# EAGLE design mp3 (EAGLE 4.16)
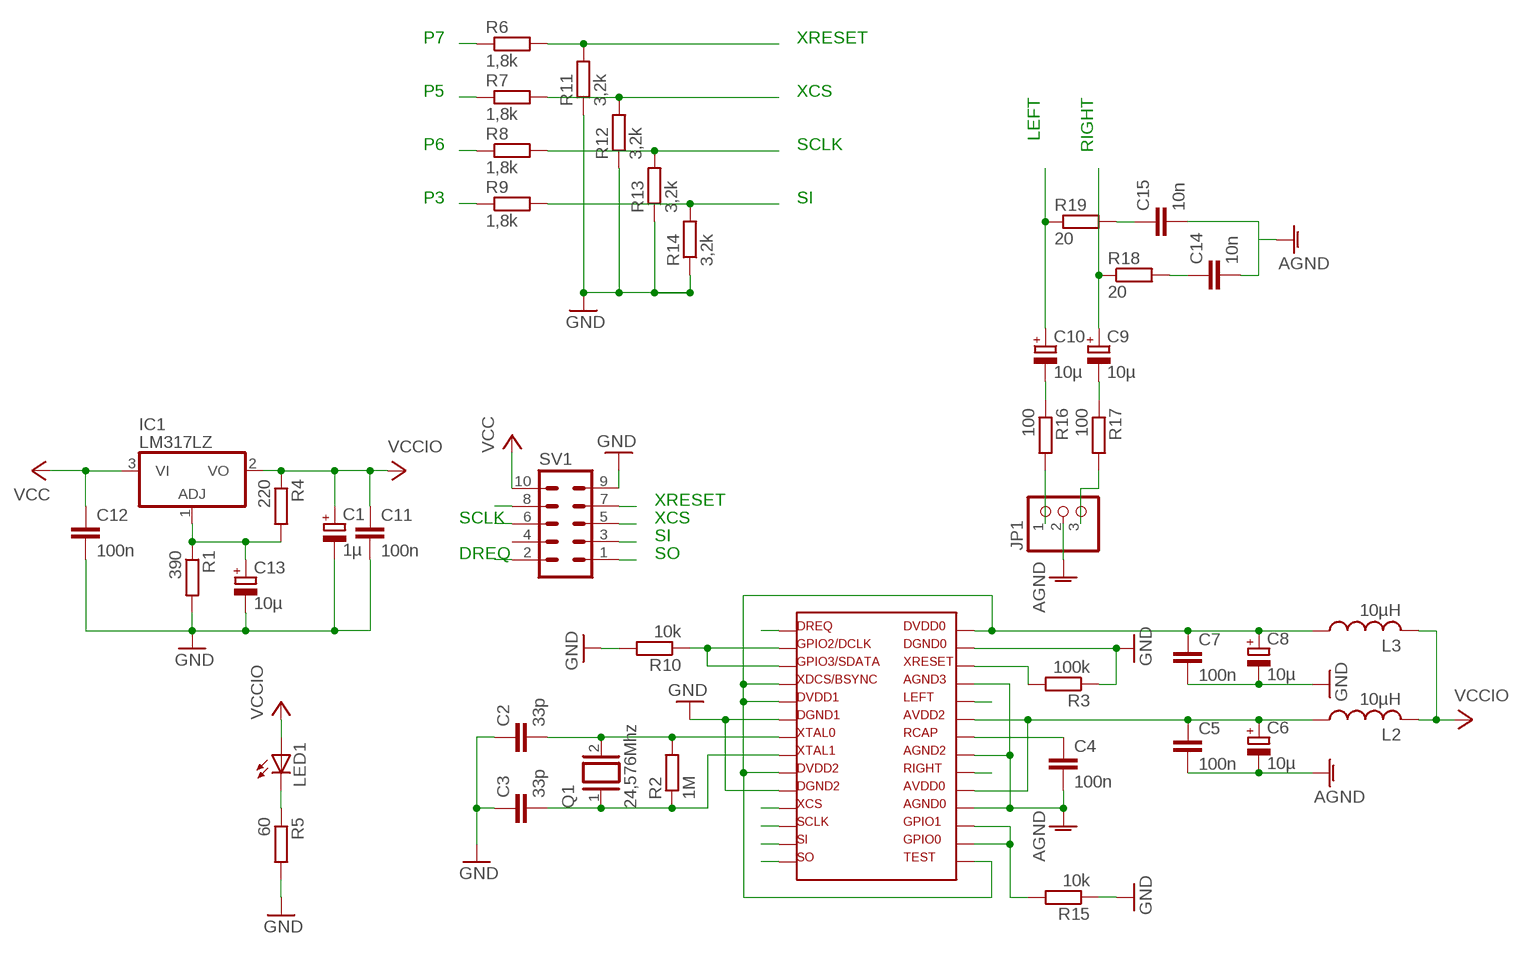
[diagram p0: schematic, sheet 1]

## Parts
C1  1µ  CPOL-EUE1.8-4  [E1,8-4]
C2  33p  C-EUC1206  [C1206]
C3  33p  C-EUC1206  [C1206]
C4  100n  C-EUC1206  [C1206]
C5  100n  C-EUC1206  [C1206]
C6  10µ  CPOL-EUE1.8-4  [E1,8-4]
C7  100n  C-EUC1206  [C1206]
C8  10µ  CPOL-EUE1.8-4  [E1,8-4]
C9  10µ  CPOL-EUE2.5-6  [E2,5-6]
C10  10µ  CPOL-EUE2.5-6  [E2,5-6]
C11  100n  C-EUC1206  [C1206]
C12  100n  C-EUC1206  [C1206]
C13  10µ  CPOL-EUE1.8-4  [E1,8-4]
C14  10n  C-EUC1206  [C1206]
C15  10n  C-EUC1206  [C1206]
IC1  LM317LZ  [TO92]
JP1  PINHD-1X3  [1X03]
L2  10µH  L-US0207/12  [0207/12]
L3  10µH  L-US0207/12  [0207/12]
LED1  LED3MM  [LED3MM]
Q1  24,576Mhz  XTAL/S  [QS]
R1  390  R-EU_M1206  [M1206]
R2  1M  R-EU_M1206  [M1206]
R3  100k  R-EU_M1206  [M1206]
R4  220  R-EU_M1206  [M1206]
R5  60  R-EU_M1206  [M1206]
R6  1,8k  R-EU_M1206  [M1206]
R7  1,8k  R-EU_M1206  [M1206]
R8  1,8k  R-EU_M1206  [M1206]
R9  1,8k  R-EU_M1206  [M1206]
R10  10k  R-EU_M1206  [M1206]
R11  3,2k  R-EU_M1206  [M1206]
R12  3,2k  R-EU_M1206  [M1206]
R13  3,2k  R-EU_M1206  [M1206]
R14  3,2k  R-EU_M1206  [M1206]
R15  10k  R-EU_M1206  [M1206]
R16  100  R-EU_M1206  [M1206]
R17  100  R-EU_M1206  [M1206]
R18  20  R-EU_M1206  [M1206]
R19  20  R-EU_M1206  [M1206]
SV1  ML10  [ML10]
U$1  VS1011  [SOIC-28]

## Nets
AGND: C4.2 C5.2 C6.- C14.2 C15.2 JP1.2 U$1.18 U$1.21 U$1.25
AVDD: C5.1 C6.+ L2.1 U$1.19 U$1.23
DREQ: SV1.2 U$1.1
DVDD: C7.1 C8.+ L3.1 U$1.4 U$1.5 U$1.9 U$1.15 U$1.28
GND: C1.- C2.1 C3.1 C7.2 C8.- C11.2 C12.2 C13.- R1.2 R3.1 R5.2 R10.2 R11.1 R12.1 R13.1 R14.1 R15.1 SV1.9 U$1.6 U$1.10 U$1.27
LEFT: C10.+ R19.1 U$1.24
N$1: C2.2 Q1.2 R2.2 U$1.7
N$2: C3.2 Q1.1 R2.1 U$1.8
N$3: C10.- R16.1
N$4: C4.1 U$1.22
N$5: JP1.3 R17.2
N$6: C13.+ IC1.1(ADJ) R1.1 R4.2
N$10: C9.- R17.1
N$11: LED1.K(C) R5.1
N$12: R10.1 U$1.2 U$1.3
N$13: R15.2 U$1.16 U$1.17
N$14: C15.1 R19.2
N$15: C14.1 R18.2
N$16: JP1.1 R16.2
P3: R9.1 SV1.3
P5: R7.1 SV1.5
P6: R8.1 SV1.6
P7: R6.1 SV1.7
P8: SV1.8
RIGHT: C9.+ R18.1 U$1.20
SCLK: R8.2 R13.2 U$1.12
SI: R9.2 R14.2 U$1.13
SO: SV1.1 U$1.14
VCC: C12.1 IC1.3(VI) SV1.10
VCCIO: C1.+ C11.1 IC1.2(VO) L2.2 L3.2 LED1.A R4.1
XCS: R7.2 R12.2 U$1.11
XRESET: R3.2 R6.2 R11.2 U$1.26
Unconnected: SV1.4

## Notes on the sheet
- P7 | XRESET
- P5 | XCS | LEFT | RIGHT
- P6 | SCLK
- P3 | SI
- XRESET
- SCLK | XCS
- SI
- DREQ | SO

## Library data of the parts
C1 C6 C8-C10 C13 = rcl:CPOL-EU: POLARIZED CAPACITOR, European symbol
C2-C5 C7 C11 C12 C14 C15 = rcl:C-EU: CAPACITOR, European symbol
IC1 = linear:*317: Positive VOLTAGE REGULATOR
JP1 = pinhead:PINHD-1X3: PIN HEADER
L2 L3 = rcl:L-US: INDUCTOR, American symbol
LED1 = led:LED: LED
Q1 = special:XTAL/S: CRYSTAL
R1-R19 = rcl:R-EU_: RESISTOR, European symbol
SV1 = con-ml:ML10: HARTING
U$1 = vs10xx:VS1011

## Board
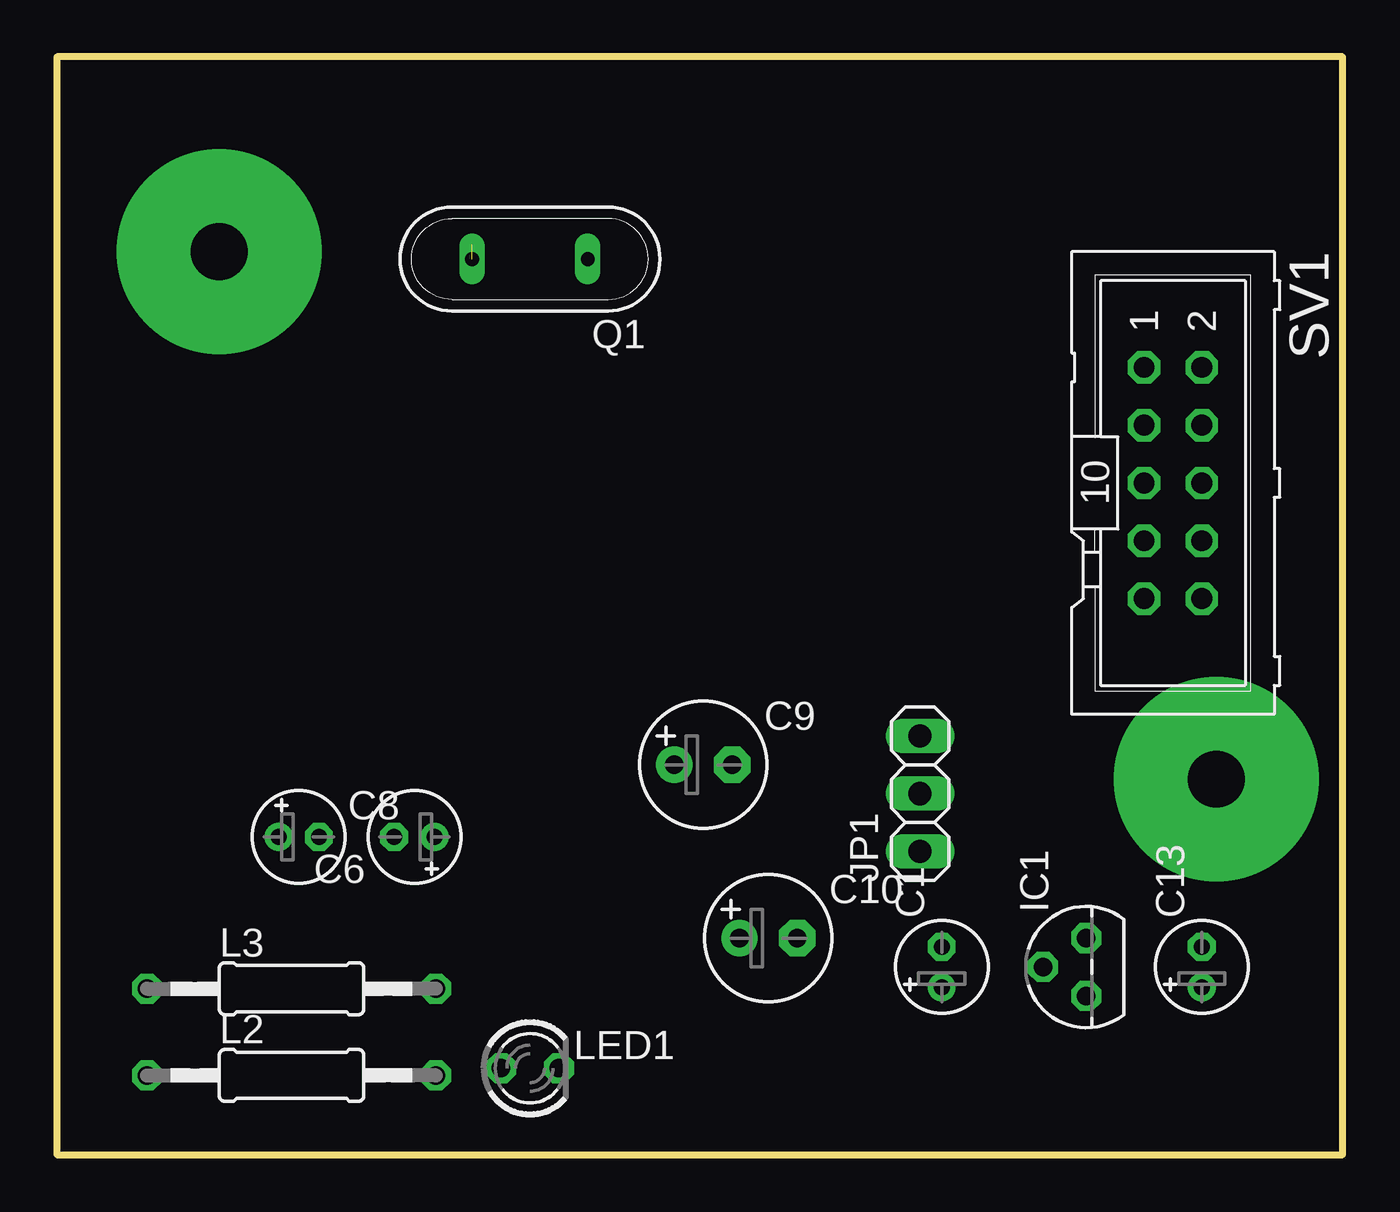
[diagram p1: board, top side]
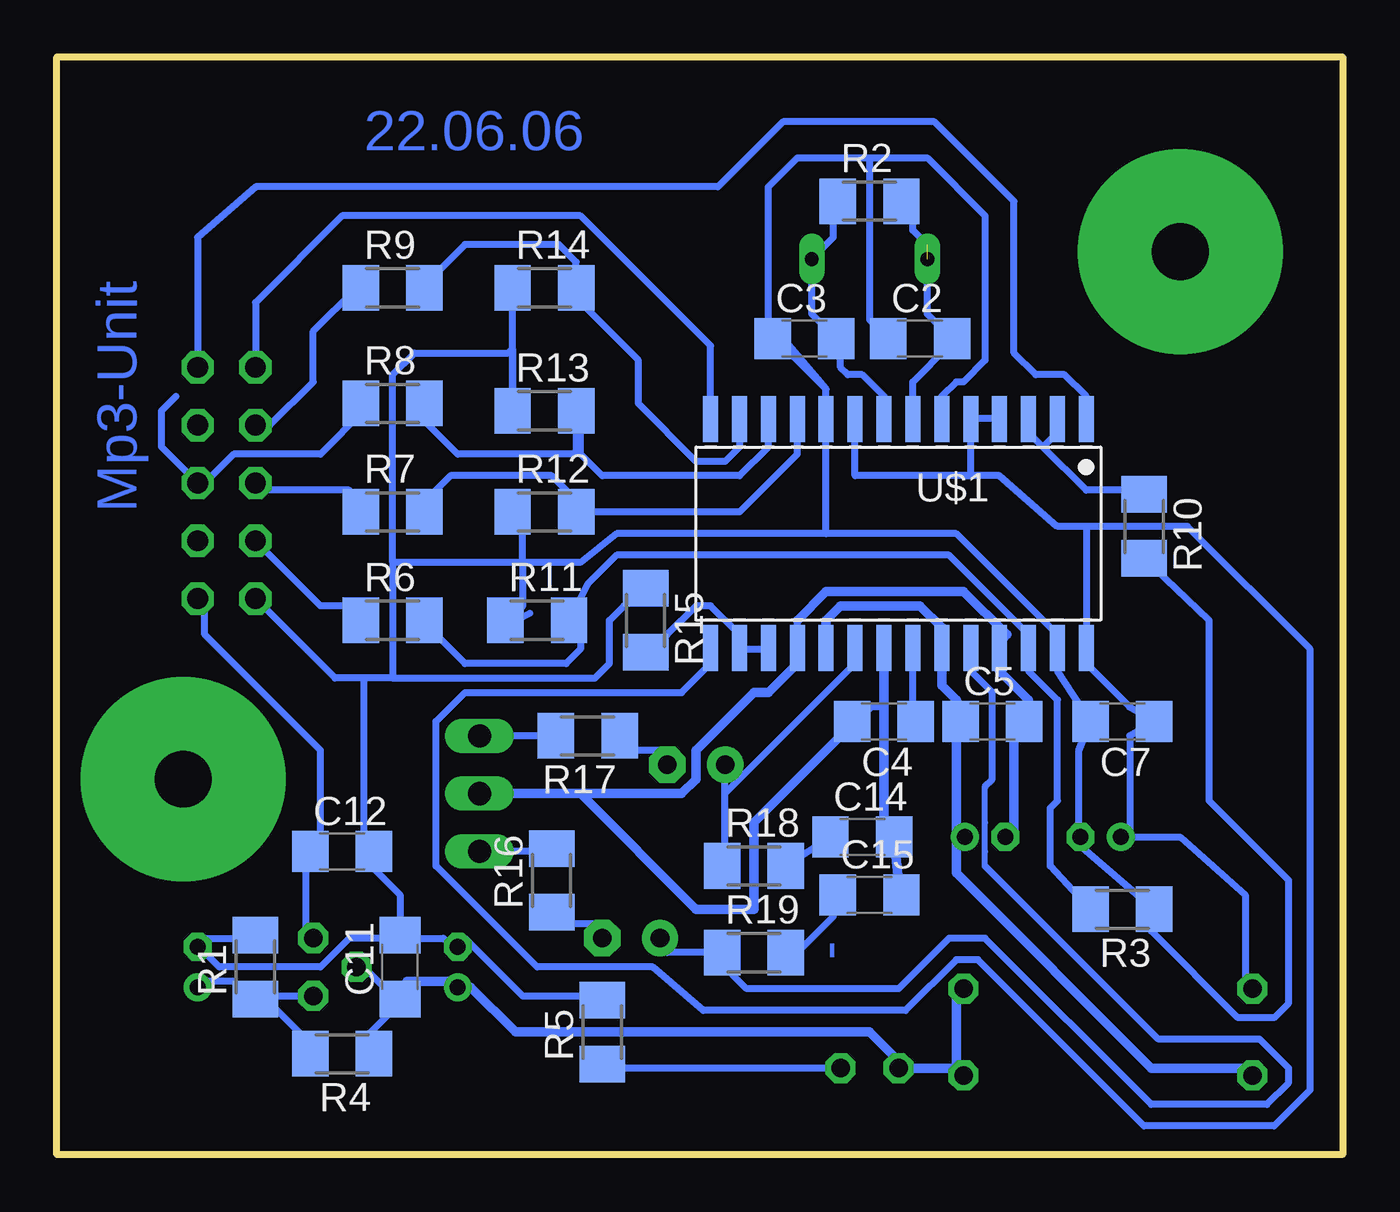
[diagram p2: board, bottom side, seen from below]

Size 56.5 x 48.25 mm. Coordinates in mm from the lower left corner, seen from the top.
Outline: 0,0 56.5,0 56.5,48.25 0,48.25 0,0
Copper layers (1*16): Top 0.035mm / dielectric 1.5mm / Bottom 0.035mm
Design rules "default": minimum track width 10mil, minimum drill 24mil, track to track 8mil, track to pad 8mil, pad to pad 8mil, via to via 8mil, smd to smd 8mil, copper to edge 40mil, drill to drill 8mil, minimum pad ring 10mil, minimum via ring 8mil, stop-mask expansion 4mil, vias tented up to drill 0mil, thermal gap 10mil

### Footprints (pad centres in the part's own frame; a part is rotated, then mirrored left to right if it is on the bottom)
E1,8-4 = drill 0.711 pad 1.168 round: + -0.889,0 | drill 0.711 pad 1.168 octagon: - 0.889,0
C1206 = smd 1.6 x 1.8: 1 -1.4,0; 2 1.4,0
E2,5-6 = drill 0.813 pad 1.6 round: + -1.27,0 | drill 0.813 pad 1.6 octagon: - 1.27,0
TO92 = drill 0.813 octagon: 1 -1.27,0; 2 0,1.905; 3 1.27,0
1X03 = drill 1.016 long: 1 -2.54,0; 2 0,0; 3 2.54,0
0207/12 = drill 0.813 octagon: 1 -6.35,0; 2 6.35,0
LED3MM = drill 0.813 octagon: A -1.27,0; K 1.27,0
QS = drill 0.61 long: 1 -2.54,0; 2 2.54,0
M1206 = smd 1.6 x 2: 1 -1.4,0; 2 1.4,0
ML10 = drill 0.914 pad 1.422 octagon: 1 -5.08,-1.27; 2 -5.08,1.27; 3 -2.54,-1.27; 4 -2.54,1.27; 5 0,-1.27; 6 0,1.27; 7 2.54,-1.27; 8 2.54,1.27; 9 5.08,-1.27; 10 5.08,1.27
SOIC-28 = smd 0.66 x 2.032: 1 -6.985,-5.029; 2 -5.715,-5.029; 3 -4.445,-5.029; 4 -3.175,-5.029; 5 -1.905,-5.029; 6 -0.635,-5.029; 7 0.635,-5.029; 8 1.905,-5.029; 9 3.175,-5.029; 10 4.445,-5.029; 11 5.715,-5.029; 12 6.985,-5.029; 13 8.255,-5.029; 14 9.525,-5.029; 15 9.525,5.029; 16 8.255,5.029; 17 6.985,5.029; 18 5.715,5.029; 19 4.445,5.029; 20 3.175,5.029; 21 1.905,5.029; 22 0.635,5.029; 23 -0.635,5.029; 24 -1.905,5.029; 25 -3.175,5.029; 26 -4.445,5.029; 27 -5.715,5.029; 28 -6.985,5.029

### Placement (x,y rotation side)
C1  38.89,8.25 90 top
C2  18.57,35.87 0 bottom
C3  23.65,35.87 0 bottom
C4  20.15,19.04 180 bottom
C5  15.39,19.04 0 bottom
C6  15.71,13.96 180 top
C7  9.68,19.04 180 bottom
C8  10.63,13.96 0 top
C9  28.41,17.14 0 top
C10  31.27,9.52 0 top
C11  41.43,8.25 90 bottom
C12  43.97,13.33 0 bottom
C13  50.32,8.25 90 top
C14  21.11,13.96 0 bottom
C15  20.79,11.43 0 bottom
IC1  45.24,8.25 90 top
JP1  37.94,15.87 90 top
L2  10.31,3.49 0 top
L3  10.31,7.3 0 top
LED1  20.79,3.8 0 top
Q1  20.79,39.37 180 top
R1  47.78,8.25 90 bottom
R2  20.79,41.91 0 bottom
R3  9.68,10.79 180 bottom
R4  43.97,4.44 180 bottom
R5  32.54,5.39 90 bottom
R6  41.75,23.49 0 bottom
R7  41.75,28.25 0 bottom
R8  41.75,33.02 0 bottom
R9  41.75,38.1 0 bottom
R10  8.72,27.62 270 bottom
R11  35.4,23.49 0 bottom
R12  35.08,28.25 0 bottom
R13  35.08,32.7 0 bottom
R14  35.08,38.1 0 bottom
R15  30.63,23.49 270 bottom
R16  34.76,12.06 90 bottom
R17  33.17,18.41 180 bottom
R18  25.87,12.7 0 bottom
R19  25.87,8.88 0 bottom
SV1  49.05,29.52 270 top
U$1  18.25,27.3 180 bottom

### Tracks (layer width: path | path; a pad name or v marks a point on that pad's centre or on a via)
AGND
  Bottom 0.305: 19.52,12.06 19.52,11.11 C15.2 | 20.15,19.68 20.79,19.68 | C14.2 20.15,13.33 | 14.44,18.41 C5.2 13.99,19.23 13.8,20 | 14.44,13.96 C6.- | 15.08,21.27 U$1.25 14.76,22.86 | 23.96,23.49 U$1.18 23.96,21.59 | C4.2 22.06,18.41
  Bottom 0.406: 19.52,12.06 C14.2 | 20.79,19.68 C4.2 | 20.15,13.33 20.15,19.68 U$1.21 | 14.44,18.41 14.44,13.96 | 15.08,21.27 13.8,20 | 23.96,23.49 22.69,24.76 16.66,24.76 14.76,22.86 | 33.49,15.87 29.04,15.87 28.41,16.5 28.41,17.77 25.87,20.32 25.23,20.32 23.96,21.59 | 33.49,15.87 JP1.2 | 22.06,18.41 25.87,14.6 25.87,10.79 28.41,10.79 33.49,15.87
AVDD
  Bottom 0.305: 16.98,18.41 C5.1 | U$1.23 17.61,23.17 | 16.98,13.96 C6.+
  Bottom 0.406: 16.98,18.41 16.98,13.96 16.98,12.38 8.41,3.8 4.28,3.8 L2.1 | U$1.23 17.61,20.63 16.98,20 C5.1 | 17.61,23.17 18.57,24.12 22.06,24.12 22.69,23.49 U$1.19
DREQ
  Bottom 0.305: U$1.1 11.27,33.33 12.22,34.29 13.49,34.29 14.44,35.24 14.44,41.91 17.93,45.4 24.6,45.4 27.46,42.54 47.78,42.54 50.32,40.32 SV1.2
DVDD
  Bottom 0.305: 9.36,13.96 9.36,18.41 C7.1 9.36,19.68 11.27,21.59 U$1.28 11.27,22.86 11.27,27.62 | 9.36,13.96 7.14,13.96 4.28,11.43 4.28,7.62 L3.1 | 9.36,13.96 C8.+ | U$1.15 27.77,21.59 29.04,20.32 38.57,20.32 39.84,19.04 39.84,12.7 35.4,8.25 30.31,8.25 28.09,6.35 19.2,6.35 16.98,8.57 16.03,8.57 8.72,1.26 3.01,1.26 1.42,2.85 1.42,22.22 6.82,27.62 11.27,27.62 | 11.27,27.62 12.54,27.62 15.08,29.84 16.66,29.84 | U$1.9 21.42,29.84 17.61,29.84 16.66,29.84 | 16.66,29.84 16.34,29.84 U$1.5 16.34,32.38 15.13,32.38 U$1.4
GND
  Bottom 0.305: R1.2 48.73,9.52 50,9.52 C13.- 50.64,8.88 50,8.88 49.37,8.25 44.92,8.25 43.65,9.52 41.75,9.52 41.43,9.84 | R5.2 33.49,6.98 36.03,6.98 38.57,9.52 C1.- 39.52,9.52 41.11,9.52 C11.2 41.43,9.84 | 36.03,26.03 36.03,27.3 R12.1 | 43.02,20.95 44.29,20.95 SV1.9 | 41.75,20.95 43.02,20.95 | 41.75,20.95 32.85,20.95 32.22,21.59 32.22,23.49 31.58,24.12 R15.1 | 41.75,26.03 41.75,20.95 | 36.03,26.03 36.03,24.12 R11.1 36.35,23.49 35.71,23.81 | 36.03,26.03 41.75,26.03 | 43.02,20.95 43.02,13.96 C12.2 42.7,12.7 41.43,11.43 41.43,9.84 | 11.58,13.96 11.58,17.77 C7.2 12.54,21.27 U$1.27 12.54,22.86 16.98,27.3 22.69,27.3 | 11.58,13.96 11.58,13.65 R3.1 8.41,9.84 4.6,6.03 3.01,6.03 2.38,6.66 2.38,12.06 5.87,15.55 5.87,23.49 R10.2 | 11.58,13.96 C8.- | 20.79,43.81 20.79,40.95 | 20.79,40.95 20.79,40 | 22.69,27.3 31.9,27.3 33.49,26.03 36.03,26.03 | 20.79,43.81 18.25,43.81 15.71,41.27 15.71,34.92 16.66,33.97 16.98,33.97 17.61,33.33 U$1.6 | 20.79,43.81 23.96,43.81 25.23,42.54 25.23,36.19 24.92,35.87 | R14.1 36.48,37.91 36.35,37.78 36.48,37.65 R13.1 36.48,35.43 36.66,35.24 40.79,35.24 41.75,34.29 41.75,26.03 | 22.69,31.11 U$1.10 22.69,33.65 | C2.1 20.79,36.7 20.79,40.95 | 22.69,33.65 24.6,35.87 24.92,35.87 | 24.92,35.87 C3.1 | 22.69,27.3 22.69,31.11 | 22.69,31.11 22.69,33.65 | 22.69,33.65 24.92,35.87
LEFT
  Bottom 0.254: 15.71,16.19 15.71,14.6 15.71,13.33 15.71,12.7
  Bottom 0.305: C10.+ 29.68,8.88 R19.1 27.27,8.75 27.46,8.57 26.19,7.3 19.52,7.3 17.3,9.52 15.71,9.52 8.41,2.22 3.33,2.22 2.38,3.17 2.38,3.8 3.65,5.08 8.09,5.08 15.71,12.7 | U$1.24 16.34,21.27 15.39,20.32 15.39,16.5 15.71,16.19
N$1  (1 unrouted)
  Bottom 0.305: 18.25,40 18.88,40.64 18.88,41.27 R2.2 | Q1.2 18.25,36.96 C2.2 17.3,35.74 17.3,35.56 18.88,33.97 U$1.7
N$2
  Bottom 0.305: 22.69,41.27 R2.1 22.38,41.72 22.38,40.32 Q1.1 23.33,36.96 C3.2 22.06,35.69 22.06,34.6 21.74,34.29 21.11,34.29 20.15,33.33 U$1.8
N$3
  Bottom 0.305: R16.1 34.12,10.15 32.85,10.15 C10.-
N$4
  Bottom 0.305: C4.1 18.88,19.68 U$1.22
N$5
  Bottom 0.305: R17.2 JP1.3
N$6
  Bottom 0.305: R4.2 45.55,5.08 46.83,6.35 R1.1 | C13.+ 50,7.62 48.73,7.62 R1.1 | IC1.1 46.83,6.98 R1.1
N$8  (via drill 2.5 pad 9)
  other vias: 50.95,16.5
N$9  (via drill 2.5 pad 9)
  other vias: 7.14,39.68
N$10
  Bottom 0.305: R17.1 31.58,17.77 29.68,17.77 C9.-
N$11
  Bottom 0.305: R5.1 31.58,3.8 LED1.K
N$12
  Bottom 0.305: 13.17,31.11 13.8,31.75 U$1.3 | 13.17,31.11 11.27,29.2 9.36,29.2 R10.1 | 13.17,31.11 12.54,31.75 U$1.2
N$13
  Bottom 0.305: R15.2 29.68,22.86 28.41,24.12 27.77,24.12 26.5,22.86 U$1.16 26.5,22.22 25.23,22.22 U$1.17
N$14
  Bottom 0.305: C15.1 22.38,10.47 23.96,8.88 R19.2
N$15
  Bottom 0.305: R18.2 C14.1
N$16
  Bottom 0.305: R16.2 35.4,13.33 JP1.1
P3
  Bottom 0.305: SV1.3 47.14,32.06 45.24,33.97 45.24,36.19 43.33,38.1 R9.1
P5
  Bottom 0.305: R7.1 43.65,29.2 47.46,29.2 SV1.5
P6
  Bottom 0.305: 51.27,33.33 51.91,32.7 51.91,31.11 SV1.6 50,29.52 48.73,30.79 44.92,30.79 43.02,32.7 43.15,32.83 R8.1
P7
  Bottom 0.305: R6.1 43.65,24.12 44.92,24.12 SV1.7
RIGHT
  Bottom 0.305: 27.14,15.87 27.14,13.33 R18.1 | 27.14,15.87 C9.+ | 27.14,15.87 21.42,21.59 U$1.20
SCLK
  Bottom 0.305: R8.2 40.34,32.83 40.48,32.7 40.48,32.38 38.89,30.79 33.81,30.79 33.68,30.92 R13.2 33.49,31.75 33.49,30.79 32.54,29.84 26.5,29.84 25.23,31.11 U$1.12
SI
  Bottom 0.305: R9.2 40.48,38.1 38.57,40 34.44,40 33.68,39.24 R14.2 33.68,37.91 33.81,37.78 30.95,34.92 30.95,33.02 28.41,30.47 27.14,30.47 26.5,31.11 U$1.13 26.5,32.38
SO
  Bottom 0.305: U$1.14 27.77,35.56 33.49,41.27 43.97,41.27 47.78,37.46 SV1.1
VCC
  Bottom 0.305: IC1.3 45.55,9.52 45.55,12.7 C12.1 44.92,13.96 44.92,17.77 50,22.86 50,24.12 SV1.10
VCCIO
  Bottom 0.305: 16.98,6.98 L3.2 | L2.2 16.98,3.8 | C11.1 41.75,6.35 43.02,5.08 R4.1 | 41.11,7.62 C11.1 | IC1.2 43.02,8.25 41.75,6.98 C11.1 | 38.32,7.36 C1.+ | LED1.A 19.52,4.12
  Bottom 0.406: LED1.A 16.98,3.8 16.98,6.98 | 41.11,7.62 39.21,7.62 C1.+ | 38.32,7.36 36.35,5.39 20.79,5.39 19.52,4.12
XCS
  Bottom 0.305: R7.2 39.84,29.2 39.21,29.84 34.76,29.84 34.12,29.2 R12.2 26.5,28.25 23.96,30.79 U$1.11 23.96,32.38
XRESET
  Bottom 0.305: R6.2 39.84,22.86 38.57,21.59 34.12,21.59 33.49,22.22 33.49,22.86 R11.2 33.17,25.08 31.9,26.35 17.3,26.35 13.8,22.86 U$1.26 13.8,21.27 12.54,20 12.54,15.55 12.85,15.23 12.85,12.7 R3.2

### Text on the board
Bottom: 22.06.06 | Mp3-Unit | -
